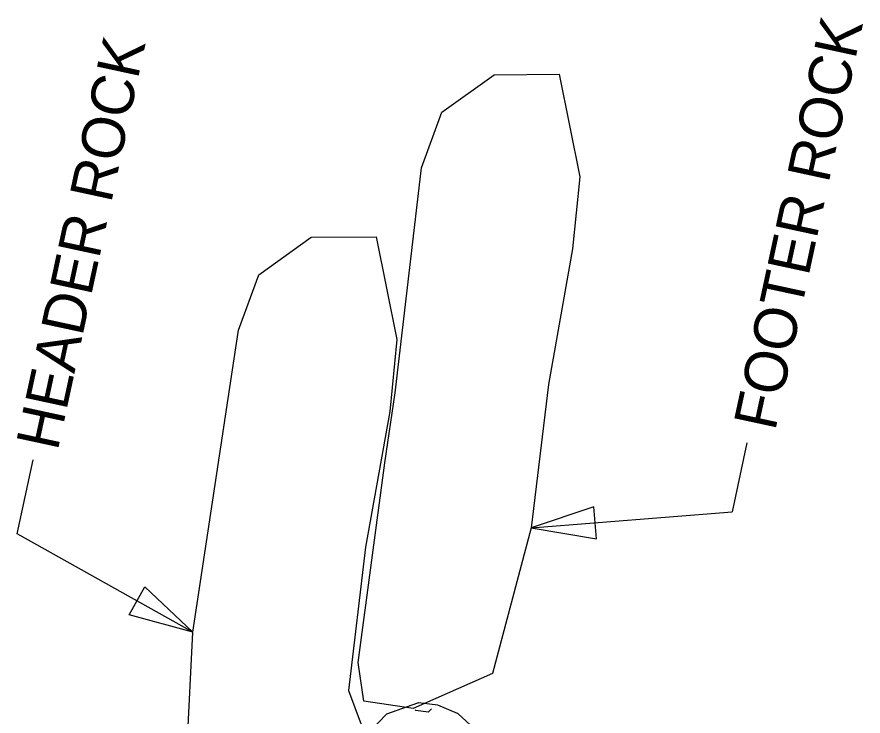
# Model space of a CAD drawing. Extents: x 2126110 to 2128246, y 1804858 to 1811658.
# Drawn here: x 2127091.8 to 2127488.8, y 1811183.7 to 1811511.7 of the extents above; entities that cross this region are included whole.
import ezdxf

# ---------------------------------------------------------------- set-up
doc = ezdxf.new("R2010")
doc.units = 0
doc.layers.add('42', color=7, linetype='Continuous')
doc.layers.add('Old_Level_1', color=7, linetype='Continuous')

msp = doc.modelspace()

# ---------------------------------------------------------------- linework, layer by layer
at = {"layer": '42'}
for points in [[(2127352.53, 1811402.9), (2127341.22, 1811339.23), (2127333.15, 1811272.01), (2127314.87, 1811203.68), (2127277.67, 1811187.28), (2127254.61, 1811190.74), (2127251.93, 1811208.8), (2127264.37, 1811302.59), (2127269.28, 1811335.37), (2127281.62, 1811440.95), (2127291.12, 1811467.02), (2127315.65, 1811484.56), (2127315.65, 1811484.56), (2127346.16, 1811484.77), (2127355.86, 1811436.63), (2127352.53, 1811402.9)], [(2127266.71, 1811326.65), (2127255.4, 1811262.98), (2127247.34, 1811195.76), (2127253.33, 1811179.73), (2127240.94, 1811164.38), (2127226.84, 1811146.69), (2127213.74, 1811143.24), (2127200.07, 1811153), (2127172.52, 1811161.28), (2127171.66, 1811169.66), (2127174.26, 1811223.13), (2127180.81, 1811265.39), (2127195.8, 1811364.7), (2127205.3, 1811390.77), (2127229.84, 1811408.31), (2127229.84, 1811408.31), (2127260.34, 1811408.52), (2127270.05, 1811360.38), (2127266.71, 1811326.65)]]:
    msp.add_lwpolyline(points, dxfattribs=at)
at = {"layer": 'Old_Level_1'}
for p, q in [((2127434.29, 1811311.91), (2127427.31, 1811279.58)), ((2127099.31, 1811303.91), (2127091.83, 1811269.29)), ((2127333.15, 1811272.01), (2127427.31, 1811279.58)), ((2127174.26, 1811223.13), (2127091.84, 1811269.29)), ((2127279.82, 1811189.82), (2127265.24, 1811184.63)), ((2127312.31, 1811172.57), (2127298.84, 1811184.79)), ((2127264.85, 1811184.38), (2127255.69, 1811174.7))]:
    msp.add_line(p, q, dxfattribs=at)
for points in [[(2127352.53, 1811402.9), (2127341.22, 1811339.23), (2127333.15, 1811272.01), (2127314.87, 1811203.68), (2127277.67, 1811187.28), (2127254.61, 1811190.74), (2127251.93, 1811208.8), (2127264.37, 1811302.59), (2127269.28, 1811335.37), (2127281.62, 1811440.95), (2127291.12, 1811467.02), (2127315.65, 1811484.56), (2127315.65, 1811484.56), (2127346.16, 1811484.77), (2127355.86, 1811436.63), (2127352.53, 1811402.9)], [(2127266.71, 1811326.65), (2127255.4, 1811262.98), (2127247.34, 1811195.76), (2127253.33, 1811179.73), (2127240.94, 1811164.38), (2127226.84, 1811146.69), (2127213.74, 1811143.24), (2127200.07, 1811153), (2127172.52, 1811161.28), (2127171.66, 1811169.66), (2127174.26, 1811223.13), (2127180.81, 1811265.39), (2127195.8, 1811364.7), (2127205.3, 1811390.77), (2127229.84, 1811408.31), (2127229.84, 1811408.31), (2127260.34, 1811408.52), (2127270.05, 1811360.38), (2127266.71, 1811326.65)], [(2127298.55, 1811184.98), (2127289.34, 1811188.78), (2127280.28, 1811189.87)], [(2127286.34, 1811187.06), (2127284.67, 1811185.54), (2127278.92, 1811186.4), (2127278.61, 1811186.71)]]:
    msp.add_lwpolyline(points, dxfattribs=at)
for points in [[(2127362.45, 1811281.89), (2127333.15, 1811272.01), (2127363.65, 1811266.94)], [(2127151.75, 1811244.33), (2127174.26, 1811223.13), (2127144.42, 1811231.24)]]:
    msp.add_lwpolyline(points, close=True, dxfattribs=at)
for centre, start, end in [((2127280.16, 1811188.88), 83.1121, 109.586), ((2127265.58, 1811183.69), 109.586, 136.5427), ((2127298.17, 1811184.05), 47.7681, 67.5962)]:
    msp.add_arc(centre, 1, start, end, dxfattribs=at)

# ---------------------------------------------------------------- texts
for s, p in [('FOOTER ROCK', (2127447.51, 1811317.07)), ('HEADER ROCK', (2127110.88, 1811307.73))]:
    msp.add_text(s, height=20, rotation=77.8264, dxfattribs=at).set_placement(p)

doc.saveas('drawing.dxf')
